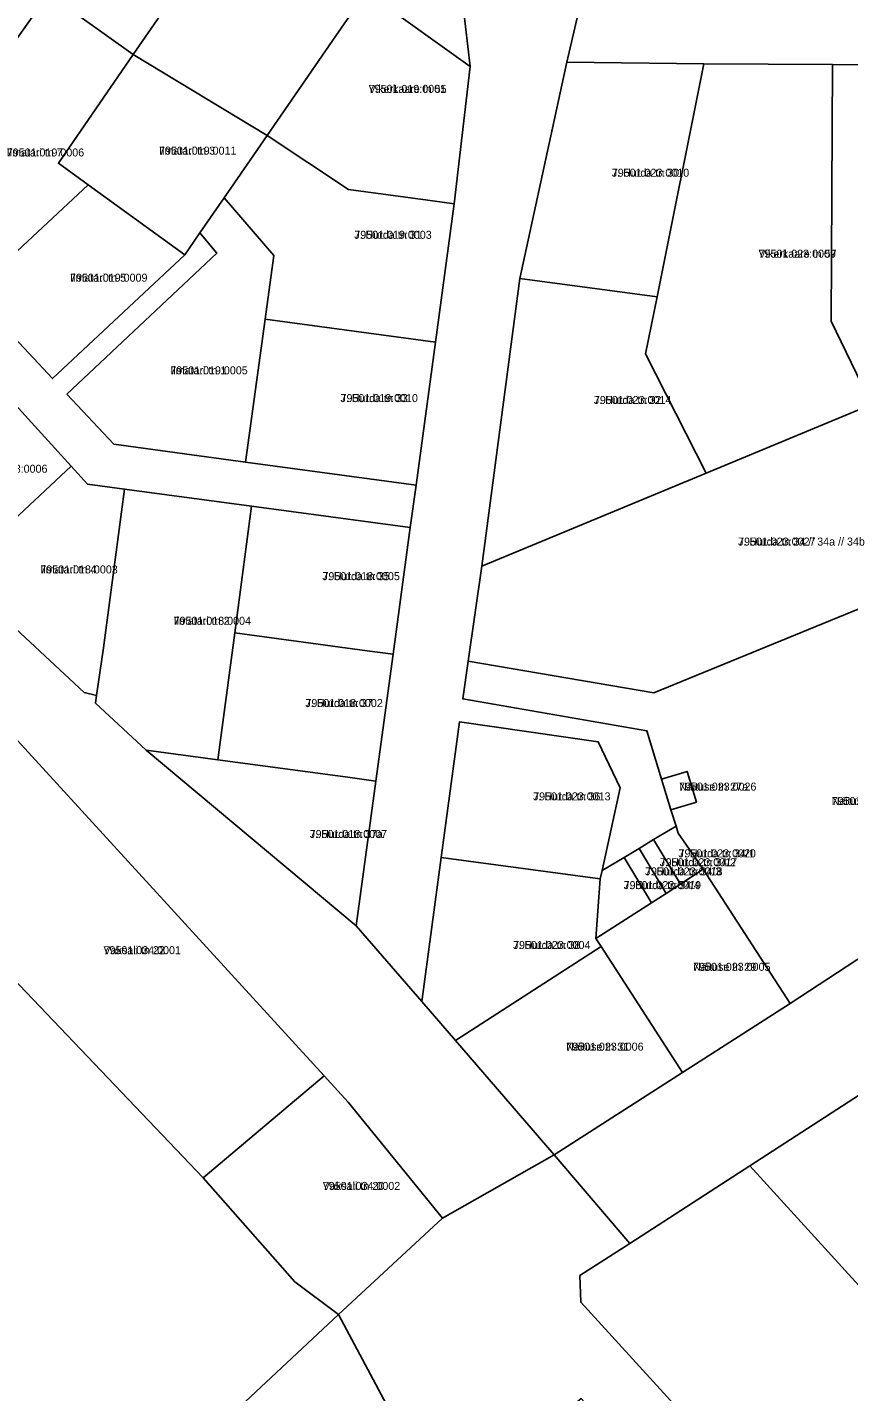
# Model space of a CAD drawing. Extents: x 643847 to 663718, y 6468443 to 6482775.
# Drawn here: x 657926.1 to 658080, y 6473935.3 to 6474191 of the extents above; entities that cross this region are included whole.
import ezdxf

# ---------------------------------------------------------------- set-up
doc = ezdxf.new("R2010")
doc.units = 0
for name, color, linetype in [('L_AADRESS', 7, 'Continuous'), ('PIIR', 7, 'Continuous'), ('TUNNUS', 7, 'Continuous')]:
    doc.layers.add(name, color=color, linetype=linetype)

msp = doc.modelspace()

# ---------------------------------------------------------------- linework, layer by layer
at = {"layer": 'PIIR'}
for points in [[(657945.92, 6474185.91), (657930.05, 6474197.25), (657926.39, 6474199.87), (657940.58, 6474220.45), (657946.25, 6474228.68), (657965.78, 6474214.73), (657960.1, 6474206.49)], [(657965.78, 6474214.73), (657989.59, 6474197.65), (657983.91, 6474189.42), (657971.01, 6474170.74), (657945.92, 6474185.91), (657960.1, 6474206.49)], [(658052.83, 6474184.17), (658027.17, 6474184.48), (658033.15, 6474210.25), (658036.76, 6474205.47), (658046.08, 6474197.88), (658048.87, 6474196.63), (658059.17, 6474194.95), (658113.95, 6474192.61), (658142.38, 6474191.9), (658150.14, 6474187.44), (658141.91, 6474183.41), (658108.53, 6474183.8), (658077, 6474184.04)], [(657898.52, 6474159.73), (657902.18, 6474163.13), (657919.13, 6474178.84), (657917.84, 6474180.18), (657930.05, 6474197.25), (657945.92, 6474185.91), (657931.88, 6474165.52), (657937.44, 6474161.49), (657919.4, 6474144.67), (657915.75, 6474141.27)], [(658009.06, 6474183.69), (658006.06, 6474157.91), (658001.12, 6474158.59), (657986.25, 6474160.63), (657971.01, 6474170.74), (657983.91, 6474189.42), (657989.59, 6474197.65)], [(657955.57, 6474148.37), (657937.44, 6474161.49), (657931.88, 6474165.52), (657945.92, 6474185.91), (657971.01, 6474170.74), (657962.94, 6474159.05), (657958.41, 6474152.48)], [(658044.12, 6474140.49), (658018.39, 6474143.93), (658027.17, 6474184.48), (658052.83, 6474184.17)], [(658077, 6474184.04), (658076.72, 6474135.91), (658084.29, 6474120.32), (658053.28, 6474107.48), (658041.93, 6474129.79), (658044.12, 6474140.49), (658052.83, 6474184.17)], [(658108.53, 6474183.8), (658108.83, 6474145.85), (658113.9, 6474132.89), (658087.06, 6474121.47), (658084.29, 6474120.32), (658076.72, 6474135.91), (658077, 6474184.04)], [(658002.55, 6474132), (657970.64, 6474136.32), (657972.24, 6474148.22), (657962.94, 6474159.05), (657971.01, 6474170.74), (657986.25, 6474160.63), (658001.12, 6474158.59), (658006.06, 6474157.91)], [(657915.75, 6474141.27), (657919.4, 6474144.67), (657937.44, 6474161.49), (657955.57, 6474148.37), (657930.77, 6474125.18)], [(657942.25, 6474112.89), (657933.5, 6474122.26), (657961.6, 6474148.7), (657958.41, 6474152.48), (657962.94, 6474159.05), (657972.24, 6474148.22), (657970.64, 6474136.32), (657966.96, 6474109.54)], [(658018.39, 6474143.93), (658044.12, 6474140.49), (658041.93, 6474129.79), (658053.28, 6474107.48), (658011.24, 6474090.05)], [(657998.92, 6474105.22), (657966.96, 6474109.54), (657970.64, 6474136.32), (658002.55, 6474132)], [(657934.28, 6474108.76), (657912.71, 6474088.62), (657896.41, 6474106.32), (657918.14, 6474126.44)], [(658011.24, 6474090.05), (658053.28, 6474107.48), (658084.29, 6474120.32), (658087.07, 6474121.49), (658094, 6474104.11), (658101.79, 6474084.63), (658090.47, 6474080.19), (658085, 6474078.05), (658083.14, 6474082.5), (658043.49, 6474066.26), (658008.68, 6474072.21)], [(657937.34, 6474105.41), (657944.31, 6474104.47), (657940.32, 6474074.73), (657939.06, 6474065.77), (657936.69, 6474066.35), (657912.71, 6474088.62), (657934.28, 6474108.76)], [(657968.11, 6474101.28), (657964.94, 6474077.5), (657961.78, 6474053.72), (657948.35, 6474055.52), (657938.86, 6474064.34), (657939.06, 6474065.77), (657940.32, 6474074.73), (657944.31, 6474104.47)], [(657994.62, 6474073.52), (657989.73, 6474074.17), (657964.94, 6474077.5), (657968.11, 6474101.28), (657997.84, 6474097.29)], [(658008.68, 6474072.21), (658043.49, 6474066.26), (658083.14, 6474082.5), (658085, 6474078.05), (658090.47, 6474080.19), (658108.36, 6474033.79), (658069.04, 6474008.04), (658052.76, 6474033.21), (658048.03, 6474039.99), (658047.64, 6474041.28), (658046.7, 6474044.36), (658051.48, 6474045.82), (658049.73, 6474051.56), (658044.95, 6474050.1), (658042.19, 6474059.19), (658007.67, 6474065.14)], [(657964.94, 6474077.5), (657989.73, 6474074.17), (657994.62, 6474073.52), (657991.39, 6474049.74), (657986.56, 6474050.39), (657961.78, 6474053.72)], [(657981.72, 6473994.51), (657959.01, 6473975.4), (657898.98, 6474038.3), (657902.96, 6474042.49), (657905.39, 6474044.87), (657907.58, 6474047.16), (657909.89, 6474049.56), (657912.11, 6474051.87), (657914.43, 6474054.29), (657916.87, 6474056.81), (657919.97, 6474060.06), (657920.84, 6474060.96)], [(658007.09, 6474060.86), (658033.06, 6474057.11), (658037.18, 6474048.46), (658033.78, 6474032.97), (658033.42, 6474031.4), (658003.62, 6474035.42)], [(657991.39, 6474049.74), (657987.71, 6474022.64), (657948.35, 6474055.52), (657961.78, 6474053.72), (657986.56, 6474050.39)], [(658044.95, 6474050.1), (658049.73, 6474051.56), (658051.48, 6474045.82), (658046.7, 6474044.36)], [(658047.64, 6474041.28), (658048.03, 6474039.99), (658052.76, 6474033.21), (658048.46, 6474030.43), (658043.45, 6474038.78)], [(658048.46, 6474030.43), (658045.79, 6474028.71), (658040.72, 6474037.14), (658043.45, 6474038.78)], [(658045.79, 6474028.71), (658043.02, 6474026.93), (658037.91, 6474035.45), (658040.72, 6474037.14)], [(657999.99, 6474008.44), (658003.62, 6474035.42), (658033.42, 6474031.4), (658032.64, 6474020.25), (658033.62, 6474018.73), (658006.29, 6474001.13)], [(658043.02, 6474026.93), (658032.64, 6474020.25), (658033.42, 6474031.4), (658033.78, 6474032.97), (658037.91, 6474035.45)], [(658048.83, 6473995.12), (658033.62, 6474018.73), (658032.64, 6474020.25), (658043.02, 6474026.93), (658045.79, 6474028.71), (658052.76, 6474033.21), (658069.04, 6474008.04)], [(658024.78, 6473979.72), (658006.29, 6474001.13), (658033.62, 6474018.73), (658048.83, 6473995.12)], [(658061.45, 6473977.65), (658099.41, 6474002.19), (658112.11, 6474009.48), (658130.22, 6473977.9), (658091.56, 6473954.23), (658087.53, 6473958.66), (658081.88, 6473955.21)], [(657986.17, 6473989.6), (658003.89, 6473967.81), (657984.38, 6473949.8), (657976.2, 6473955.88), (657959.01, 6473975.4), (657981.72, 6473994.51)], [(658101.04, 6473873.61), (658086.01, 6473890.45), (658029.79, 6473952.09), (658029.64, 6473957.09), (658038.99, 6473963.11), (658061.45, 6473977.65), (658081.88, 6473955.21), (658087.53, 6473958.66), (658091.56, 6473954.23), (658130.32, 6473911.62), (658131.37, 6473908.78), (658120.43, 6473904.62), (658128.18, 6473883.63)], [(657931.01, 6473899.89), (657984.38, 6473949.8), (657994.38, 6473931.04), (657942.78, 6473886.38)]]:
    msp.add_lwpolyline(points, close=True, dxfattribs=at)
for points in [[(658033.15, 6474210.25), (658027.17, 6474184.48), (658018.39, 6474143.93), (658011.24, 6474090.05), (658008.68, 6474072.21), (658007.67, 6474065.14), (658042.19, 6474059.19), (658044.95, 6474050.1), (658046.7, 6474044.36), (658047.64, 6474041.28), (658043.45, 6474038.78), (658040.72, 6474037.14), (658037.91, 6474035.45), (658033.78, 6474032.97), (658037.18, 6474048.46), (658033.06, 6474057.11), (658007.09, 6474060.86), (658003.62, 6474035.42), (657999.99, 6474008.44), (657987.71, 6474022.64), (657991.39, 6474049.74), (657994.62, 6474073.52), (657997.84, 6474097.29), (657998.92, 6474105.22), (658002.55, 6474132), (658006.06, 6474157.91), (658009.06, 6474183.69), (658007.33, 6474198.74)], [(658007.33, 6474198.74), (658009.06, 6474183.69), (657989.59, 6474197.65)], [(657915.75, 6474141.27), (657930.77, 6474125.18), (657955.57, 6474148.37), (657958.41, 6474152.48), (657961.6, 6474148.7), (657933.5, 6474122.26), (657942.25, 6474112.89), (657966.96, 6474109.54), (657998.92, 6474105.22), (657997.84, 6474097.29), (657968.11, 6474101.28), (657944.31, 6474104.47), (657937.34, 6474105.41), (657934.28, 6474108.76), (657918.14, 6474126.44)], [(657912.71, 6474088.62), (657936.69, 6474066.35), (657939.06, 6474065.77), (657938.86, 6474064.34), (657948.35, 6474055.52), (657987.71, 6474022.64), (657999.99, 6474008.44), (658006.29, 6474001.13), (658024.78, 6473979.72), (658003.89, 6473967.81), (657986.17, 6473989.6), (657981.72, 6473994.51), (657920.84, 6474060.96)], [(657898.98, 6474038.3), (657959.01, 6473975.4), (657976.2, 6473955.88), (657984.38, 6473949.8), (657931.01, 6473899.89)], [(658099.41, 6474002.19), (658061.45, 6473977.65), (658038.99, 6473963.11), (658024.78, 6473979.72), (658048.83, 6473995.12), (658069.04, 6474008.04), (658108.36, 6474033.79)], [(658135.02, 6473819.12), (658029.85, 6473934.04), (658009.87, 6473917.01), (657994.38, 6473931.04), (657984.38, 6473949.8), (658003.89, 6473967.81), (658024.78, 6473979.72), (658038.99, 6473963.11), (658029.64, 6473957.09), (658029.79, 6473952.09), (658086.01, 6473890.45)]]:
    msp.add_lwpolyline(points, dxfattribs=at)

# ---------------------------------------------------------------- texts
at = {"layer": 'L_AADRESS'}
for s, p in [('Vikerkaare tn 55', (657990.04, 6474178.72)), ('Ilmatari tn 7', (657922.22, 6474166.8)), ('Ilmatari tn 3', (657950.76, 6474167.14)), ('J. Hurda tn 30', (658035.61, 6474163)), ('J. Hurda tn 31', (657987.35, 6474151.37)), ('Vikerkaare tn 57', (658063.11, 6474147.83)), ('Ilmatari tn 5', (657934.08, 6474143.33)), ('Ilmatari tn 1', (657952.87, 6474125.97)), ('J. Hurda tn 33', (657984.77, 6474120.77)), ('J. Hurda tn 32', (658032.26, 6474120.42)), ('J. Hurda tn 34 // 34a // 34b', (658059.28, 6474093.88)), ('Ilmatari tn 4', (657928.51, 6474088.66)), ('J. Hurda tn 35', (657981.38, 6474087.4)), ('Ilmatari tn 2', (657953.48, 6474079.04)), ('J. Hurda tn 37', (657978.19, 6474063.62)), ('Näituse tn 27a', (658048.21, 6474047.96)), ('J. Hurda tn 36', (658020.87, 6474046.13)), ('Näituse tn 27', (658076.81, 6474045.27)), ('J. Hurda tn 37a', (657978.99, 6474039.08)), ('J. Hurda tn 34/1', (658048.11, 6474035.45)), ('J. Hurda tn 34/3', (658041.85, 6474032.07)), ('J. Hurda tn 34/2', (658044.59, 6474033.79)), ('J. Hurda tn 34/4', (658037.83, 6474029.5)), ('Vaksali tn 22', (657940.35, 6474017.31)), ('J. Hurda tn 38', (658017.11, 6474018.28)), ('Näituse tn 29', (658050.84, 6474014.19)), ('Näituse tn 31', (658027.06, 6473999.23)), ('Vaksali tn 20', (657981.45, 6473973.13))]:
    msp.add_text(s, height=1.5, dxfattribs=at).set_placement(p)
at = {"layer": 'TUNNUS'}
for s, p in [('79501:019:0001', (657990.04, 6474178.72)), ('79501:019:0006', (657922.22, 6474166.8)), ('79501:019:0011', (657950.76, 6474167.14)), ('79501:023:0010', (658035.61, 6474163)), ('79501:019:0003', (657987.35, 6474151.37)), ('79501:023:0009', (658063.11, 6474147.83)), ('79501:019:0009', (657934.08, 6474143.33)), ('79501:019:0005', (657952.87, 6474125.97)), ('79501:019:0010', (657984.77, 6474120.77)), ('79501:023:0014', (658032.26, 6474120.42)), ('79501:018:0006', (657915.34, 6474107.53)), ('79501:023:0027', (658059.28, 6474093.88)), ('79501:018:0003', (657928.51, 6474088.66)), ('79501:018:0005', (657981.38, 6474087.4)), ('79501:018:0004', (657953.48, 6474079.04)), ('79501:018:0002', (657978.19, 6474063.62)), ('79501:023:0026', (658048.21, 6474047.96)), ('79501:023:0013', (658020.87, 6474046.13)), ('79501:023:0024', (658076.81, 6474045.27)), ('79501:018:0007', (657978.99, 6474039.08)), ('79501:023:0020', (658048.11, 6474035.45)), ('79501:023:0018', (658041.85, 6474032.07)), ('79501:023:0017', (658044.59, 6474033.79)), ('79501:023:0019', (658037.83, 6474029.5)), ('79501:034:0001', (657940.35, 6474017.31)), ('79501:023:0004', (658017.11, 6474018.28)), ('79501:023:0005', (658050.84, 6474014.19)), ('79501:023:0006', (658027.06, 6473999.23)), ('79501:034:0002', (657981.45, 6473973.13))]:
    msp.add_text(s, height=1.5, dxfattribs=at).set_placement(p)

doc.saveas('drawing.dxf')
